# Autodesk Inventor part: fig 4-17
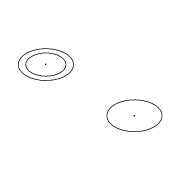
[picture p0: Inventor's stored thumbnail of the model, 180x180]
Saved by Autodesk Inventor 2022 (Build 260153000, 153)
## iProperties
Created: 2005-02
Part Number: fig 4-17
Document SubType Name: Modeling
Designer: CADCIM
Manufacturer: Standard
Standards Organization: Custom
Density: 1 g/cm^3
Material: Generic
Appearance: Default
Author: CADCIM
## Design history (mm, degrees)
sketch "Sketch1"
  geometry: C1 r 7.935 at (-23.563, 7.599); C2 r 7.935 at (12.452, 7.599); C3 r 5.782 at (-23.563, 7.599)
  constraints: 3 centre point, 1 coincident, 1 equal radius, 1 other
